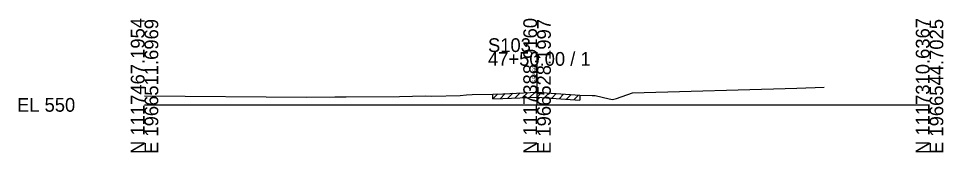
# Model space of a CAD drawing. Extents: x -26 to 163, y -10 to 45020.
# Drawn here: x -25.7 to 162.8, y 7490.3 to 7517.6 of the extents above; entities that cross this region are included whole.
import ezdxf

# ---------------------------------------------------------------- set-up
doc = ezdxf.new("R2010")
doc.units = 0
for name, color, linetype in [('RD_GPK_XS_Cell', 7, 'Continuous'), ('RD_XS_ExGround', 7, 'Continuous'), ('RD_XS_ExPaveRet', 7, 'Continuous'), ('RD_XS_TX_Elev_EX', 7, 'Continuous')]:
    doc.layers.add(name, color=color, linetype=linetype)

msp = doc.modelspace()

# ---------------------------------------------------------------- linework, layer by layer
at = {"layer": 'RD_GPK_XS_Cell'}
for p, q in [((80, 7500), (80, 7510.76)), ((0, 7500), (80, 7500)), ((80, 7500), (160, 7500))]:
    msp.add_line(p, q, dxfattribs=at)
at = {"layer": 'RD_XS_ExGround'}
for p, q in [((0, 7501.87), (33.06, 7501.6)), ((51.93, 7501.71), (57.28, 7501.81)), ((57.28, 7501.81), (58.55, 7501.79)), ((58.55, 7501.79), (64.35, 7501.92)), ((64.35, 7501.92), (65.65, 7502.02)), ((65.65, 7502.02), (66.76, 7502.09)), ((66.76, 7502.09), (70.99, 7502.21)), ((70.99, 7502.21), (73.02, 7502.28)), ((73.02, 7502.28), (80.05, 7502.56)), ((80.05, 7502.56), (81.93, 7502.44)), ((81.93, 7502.44), (88.75, 7501.97)), ((88.75, 7501.97), (91.22, 7501.91)), ((91.22, 7501.91), (91.87, 7501.89)), ((91.87, 7501.89), (94.71, 7501.21)), ((96.16, 7501.27), (99.42, 7502.47)), ((99.42, 7502.47), (132.93, 7503.42)), ((132.93, 7503.42), (138.5, 7503.59)), ((33.06, 7501.6), (38.78, 7501.64)), ((38.78, 7501.64), (41.08, 7501.63)), ((41.08, 7501.63), (51.93, 7501.71)), ((94.71, 7501.21), (95.36, 7501.07)), ((95.36, 7501.07), (96.16, 7501.27))]:
    msp.add_line(p, q, dxfattribs=at)
at = {"layer": 'RD_XS_ExPaveRet'}
for p, q in [((70.99, 7501.21), (72.03, 7502.25)), ((70.99, 7501.21), (70.99, 7502.21)), ((72.49, 7501.26), (73.53, 7502.3)), ((73.99, 7501.32), (75.03, 7502.36)), ((75.49, 7501.38), (76.53, 7502.42)), ((76.99, 7501.44), (78.03, 7502.48)), ((78.49, 7501.5), (79.53, 7502.54)), ((79.99, 7501.56), (80.93, 7502.51)), ((81.49, 7501.47), (82.43, 7502.41)), ((82.99, 7501.37), (83.92, 7502.3)), ((84.49, 7501.26), (85.42, 7502.2)), ((85.99, 7501.16), (86.92, 7502.09)), ((87.49, 7501.05), (88.42, 7501.99)), ((88.75, 7501.97), (88.75, 7500.97)), ((70.99, 7501.21), (73.02, 7501.28)), ((73.02, 7501.28), (80.05, 7501.56)), ((80.05, 7501.56), (81.93, 7501.44)), ((81.93, 7501.44), (88.75, 7500.97))]:
    msp.add_line(p, q, dxfattribs=at)

# ---------------------------------------------------------------- texts
at = {"layer": 'RD_GPK_XS_Cell'}
for s, p in [('N 1117467.1954', (0, 7490)), ('E 1966511.6969', (2.8, 7490)), ('N 1117388.9160', (80, 7490)), ('E 1966528.1997', (82.8, 7490)), ('N 1117310.6367', (160, 7490)), ('E 1966544.7025', (162.8, 7490))]:
    msp.add_text(s, height=2.8, rotation=90, dxfattribs=at).set_placement(p)
for s, p in [('S103', (70, 7510.76)), ('47+50.00 / 1', (70, 7507.96)), ('EL 550', (-26, 7498.6))]:
    msp.add_text(s, height=2.8, dxfattribs=at).set_placement(p)
at = {"layer": 'RD_XS_TX_Elev_EX'}
msp.add_text('552.56', height=0.8, rotation=90, dxfattribs=at).set_placement((79.9, 7504.56))

doc.saveas('drawing.dxf')
